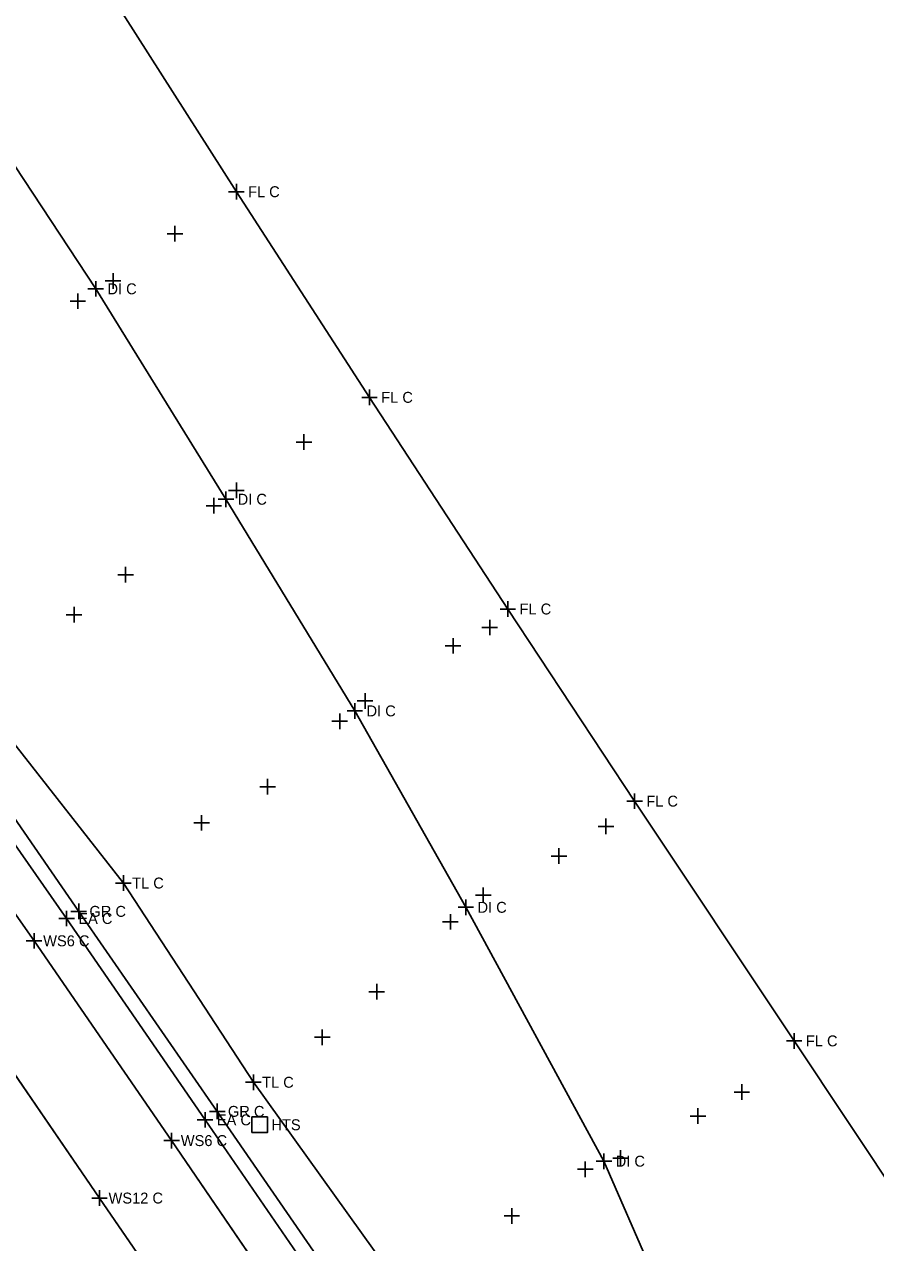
# Model space of a CAD drawing. Extents: x 1324236 to 1326110, y 459090 to 460782.
# Drawn here: x 1325473.8 to 1325582.8, y 460147.8 to 460303.9 of the extents above; entities that cross this region are included whole.
import ezdxf

# ---------------------------------------------------------------- set-up
doc = ezdxf.new("R2010")
doc.units = 0
for name, color, linetype in [('DR_X_Ditch', 7, 'Continuous'), ('DR_X_Drive_Pipe', 7, 'Continuous'), ('DR_X_Storm_Sewer', 7, 'Continuous'), ('DT_X_Contour_Major', 7, 'Continuous'), ('DV_X_Property_Line', 7, 'Continuous'), ('LT_X_Poles', 7, 'Continuous'), ('PM_X_CL_Double_Solid', 7, 'Continuous'), ('PM_X_Edge_Line', 7, 'Continuous'), ('PM_X_Parking_Lot_Stall', 7, 'Continuous'), ('PV_X_Shoulder', 7, 'Continuous'), ('RD_X_GR_Lt', 7, 'Continuous'), ('RW_X_CL', 7, 'Continuous'), ('RW_X_Esmt_SH', 7, 'Continuous')]:
    doc.layers.add(name, color=color, linetype=linetype)

msp = doc.modelspace()

# ---------------------------------------------------------------- linework, layer by layer
at = {"layer": 'DR_X_Ditch'}
msp.add_lwpolyline([(1325392.48, 460306.14), (1325394.43, 460302.92), (1325394.43, 460302.92), (1325397.79, 460297.88), (1325401.32, 460292.96), (1325401.32, 460292.96), (1325418.59, 460267.6), (1325438.59, 460238.95), (1325456.84, 460212.47), (1325475.03, 460186.5), (1325492.65, 460160.91), (1325510.99, 460134.02), (1325529.23, 460107.34), (1325547.28, 460081.09), (1325565.79, 460054.08), (1325584.28, 460027.39)], dxfattribs=at)
at = {"layer": 'DR_X_Drive_Pipe'}
for p, q in [((1325463.76, 460299.09), (1325482.93, 460270.01)), ((1325482.93, 460270.01), (1325499.6, 460243.06)), ((1325499.6, 460243.06), (1325516.1, 460215.95)), ((1325516.1, 460215.95), (1325530.31, 460190.79)), ((1325530.31, 460190.79), (1325548, 460158.27)), ((1325548, 460158.27), (1325558.06, 460135.19))]:
    msp.add_line(p, q, dxfattribs=at)
at = {"layer": 'DR_X_Storm_Sewer'}
for p, q in [((1325483.41, 460153.55), (1325465.49, 460179.7)), ((1325501.6, 460127.06), (1325483.41, 460153.55))]:
    msp.add_line(p, q, dxfattribs=at)
at = {"layer": 'DT_X_Contour_Major'}
msp.add_line((1325503.92, 460162.94), (1325503.92, 460162.94), dxfattribs=at)
msp.add_lwpolyline([(1325502.92, 460161.94), (1325502.92, 460163.94), (1325504.92, 460163.94), (1325504.92, 460161.94), (1325502.92, 460161.94)], dxfattribs=at)
at = {"layer": 'DV_X_Property_Line'}
for p, q in [((1325479.2, 460188.36), (1325479.2, 460190.36)), ((1325478.2, 460189.36), (1325480.2, 460189.36)), ((1325496.93, 460162.57), (1325496.93, 460164.57)), ((1325495.93, 460163.57), (1325497.93, 460163.57))]:
    msp.add_line(p, q, dxfattribs=at)
at = {"layer": 'LT_X_Poles'}
for points in [[(1325552.53, 460052.37), (1325537.68, 460074.22), (1325518.91, 460101.44), (1325501.6, 460127.06), (1325483.41, 460153.55), (1325465.49, 460179.7), (1325447.45, 460205.76), (1325428.78, 460232.55), (1325409.11, 460260.88), (1325391.07, 460286.18), (1325376.81, 460306.09), (1325363.64, 460323.93)], [(1325392.48, 460306.14), (1325394.43, 460302.92), (1325394.43, 460302.92), (1325397.79, 460297.88), (1325401.32, 460292.96), (1325401.32, 460292.96), (1325418.59, 460267.6), (1325438.59, 460238.95), (1325456.84, 460212.47), (1325475.03, 460186.5), (1325492.65, 460160.91), (1325510.99, 460134.02), (1325529.23, 460107.34), (1325547.28, 460081.09), (1325565.79, 460054.08), (1325584.28, 460027.39)]]:
    msp.add_lwpolyline(points, dxfattribs=at)
at = {"layer": 'PM_X_CL_Double_Solid'}
for p, q in [((1325486.43, 460305.19), (1325500.93, 460282.45)), ((1325500.93, 460282.45), (1325517.98, 460256.11)), ((1325517.98, 460256.11), (1325535.69, 460229)), ((1325535.69, 460229), (1325551.92, 460204.39)), ((1325551.92, 460204.39), (1325572.35, 460173.68)), ((1325572.35, 460173.68), (1325587.79, 460150.43))]:
    msp.add_line(p, q, dxfattribs=at)
at = {"layer": 'PM_X_Edge_Line'}
for p, q in [((1325456.84, 460212.47), (1325475.03, 460186.5)), ((1325475.03, 460186.5), (1325492.65, 460160.91)), ((1325492.65, 460160.91), (1325510.99, 460134.02))]:
    msp.add_line(p, q, dxfattribs=at)
at = {"layer": 'PM_X_Parking_Lot_Stall'}
for p, q in [((1325462.39, 460216.88), (1325480.76, 460190.27)), ((1325480.76, 460190.27), (1325498.49, 460164.65)), ((1325498.49, 460164.65), (1325517.01, 460137.81))]:
    msp.add_line(p, q, dxfattribs=at)
at = {"layer": 'PV_X_Shoulder'}
msp.add_lwpolyline([(1325398.37, 460305.69), (1325405.2, 460296.15), (1325405.2, 460296.15), (1325422.82, 460270.39), (1325442.8, 460241.71), (1325461.19, 460215.15), (1325479.2, 460189.36), (1325496.93, 460163.57), (1325515.23, 460136.92), (1325533.46, 460110.33), (1325551.75, 460083.69), (1325569.83, 460056.87), (1325588.2, 460030.22)], dxfattribs=at)
at = {"layer": 'RD_X_GR_Lt'}
for p, q in [((1325486.47, 460193.9), (1325466.66, 460219.16)), ((1325503.11, 460168.38), (1325486.47, 460193.9)), ((1325522.24, 460141.73), (1325503.11, 460168.38))]:
    msp.add_line(p, q, dxfattribs=at)
at = {"layer": 'RW_X_CL'}
for p, q in [((1325493.07, 460276.06), (1325493.07, 460278.06)), ((1325492.07, 460277.06), (1325494.07, 460277.06)), ((1325485.14, 460270.03), (1325485.14, 460272.03)), ((1325484.14, 460271.03), (1325486.14, 460271.03)), ((1325479.64, 460268.43), (1325481.64, 460268.43)), ((1325480.64, 460267.43), (1325480.64, 460269.43)), ((1325509.59, 460249.38), (1325509.59, 460251.38)), ((1325508.59, 460250.38), (1325510.59, 460250.38)), ((1325500.93, 460243.19), (1325500.93, 460245.19)), ((1325499.93, 460244.19), (1325501.93, 460244.19)), ((1325497.05, 460242.22), (1325499.05, 460242.22)), ((1325498.05, 460241.22), (1325498.05, 460243.22)), ((1325486.76, 460232.39), (1325486.76, 460234.39)), ((1325485.76, 460233.39), (1325487.76, 460233.39)), ((1325479.16, 460228.26), (1325481.16, 460228.26)), ((1325480.16, 460227.26), (1325480.16, 460229.26)), ((1325532.38, 460226.63), (1325534.38, 460226.63)), ((1325533.38, 460225.63), (1325533.38, 460227.63)), ((1325528.68, 460223.28), (1325528.68, 460225.28)), ((1325527.68, 460224.28), (1325529.68, 460224.28)), ((1325516.41, 460217.23), (1325518.41, 460217.23)), ((1325517.41, 460216.23), (1325517.41, 460218.23)), ((1325514.17, 460213.63), (1325514.17, 460215.63)), ((1325513.17, 460214.63), (1325515.17, 460214.63)), ((1325503.94, 460206.24), (1325505.94, 460206.24)), ((1325504.94, 460205.24), (1325504.94, 460207.24)), ((1325495.49, 460201.61), (1325497.49, 460201.61)), ((1325496.49, 460200.61), (1325496.49, 460202.61)), ((1325548.25, 460200.15), (1325548.25, 460202.15)), ((1325547.25, 460201.15), (1325549.25, 460201.15)), ((1325542.23, 460196.36), (1325542.23, 460198.36)), ((1325541.23, 460197.36), (1325543.23, 460197.36)), ((1325531.54, 460192.35), (1325533.54, 460192.35)), ((1325532.54, 460191.35), (1325532.54, 460193.35)), ((1325527.34, 460188.93), (1325529.34, 460188.93)), ((1325528.34, 460187.93), (1325528.34, 460189.93)), ((1325475.03, 460185.5), (1325475.03, 460187.5)), ((1325474.03, 460186.5), (1325476.03, 460186.5)), ((1325518.91, 460178.97), (1325518.91, 460180.97)), ((1325517.91, 460179.97), (1325519.91, 460179.97)), ((1325511.94, 460173.14), (1325511.94, 460175.14)), ((1325510.94, 460174.14), (1325512.94, 460174.14)), ((1325564.65, 460167.12), (1325566.65, 460167.12)), ((1325565.65, 460166.12), (1325565.65, 460168.12)), ((1325559.02, 460164.06), (1325561.02, 460164.06)), ((1325560.02, 460163.06), (1325560.02, 460165.06)), ((1325491.65, 460160.91), (1325493.65, 460160.91)), ((1325492.65, 460159.91), (1325492.65, 460161.91)), ((1325550.12, 460157.67), (1325550.12, 460159.67)), ((1325545.61, 460156.23), (1325545.61, 460158.23)), ((1325549.12, 460158.67), (1325551.12, 460158.67)), ((1325544.61, 460157.23), (1325546.61, 460157.23)), ((1325483.41, 460152.55), (1325483.41, 460154.55)), ((1325482.41, 460153.55), (1325484.41, 460153.55)), ((1325536.2, 460150.26), (1325536.2, 460152.26)), ((1325535.2, 460151.26), (1325537.2, 460151.26))]:
    msp.add_line(p, q, dxfattribs=at)
at = {"layer": 'RW_X_Esmt_SH'}
for p, q in [((1325499.93, 460282.45), (1325501.93, 460282.45)), ((1325500.93, 460281.45), (1325500.93, 460283.45)), ((1325481.93, 460270.01), (1325483.93, 460270.01)), ((1325482.93, 460269.01), (1325482.93, 460271.01)), ((1325516.98, 460256.11), (1325518.98, 460256.11)), ((1325517.98, 460255.11), (1325517.98, 460257.11)), ((1325499.6, 460242.06), (1325499.6, 460244.06)), ((1325498.6, 460243.06), (1325500.6, 460243.06)), ((1325535.69, 460228), (1325535.69, 460230)), ((1325534.69, 460229), (1325536.69, 460229)), ((1325516.1, 460214.95), (1325516.1, 460216.95)), ((1325515.1, 460215.95), (1325517.1, 460215.95)), ((1325550.92, 460204.39), (1325552.92, 460204.39)), ((1325551.92, 460203.39), (1325551.92, 460205.39)), ((1325485.47, 460193.9), (1325487.47, 460193.9)), ((1325486.47, 460192.9), (1325486.47, 460194.9)), ((1325480.76, 460189.27), (1325480.76, 460191.27)), ((1325529.31, 460190.79), (1325531.31, 460190.79)), ((1325530.31, 460189.79), (1325530.31, 460191.79)), ((1325479.76, 460190.27), (1325481.76, 460190.27)), ((1325571.35, 460173.68), (1325573.35, 460173.68)), ((1325572.35, 460172.68), (1325572.35, 460174.68)), ((1325503.11, 460167.38), (1325503.11, 460169.38)), ((1325502.11, 460168.38), (1325504.11, 460168.38)), ((1325498.49, 460163.65), (1325498.49, 460165.65)), ((1325497.49, 460164.65), (1325499.49, 460164.65)), ((1325548, 460157.27), (1325548, 460159.27)), ((1325547, 460158.27), (1325549, 460158.27))]:
    msp.add_line(p, q, dxfattribs=at)

# ---------------------------------------------------------------- texts
at = {"layer": 'DT_X_Contour_Major'}
msp.add_text('HTS', height=1.4, dxfattribs=at).set_placement((1325505.42, 460162.24))
at = {"layer": 'DV_X_Property_Line'}
for p in [(1325480.7, 460188.66), (1325498.43, 460162.87)]:
    msp.add_text('EA C', height=1.4, dxfattribs=at).set_placement(p)
at = {"layer": 'RW_X_CL'}
for s, p in [('WS6 C', (1325476.2, 460185.8)), ('WS6 C', (1325493.82, 460160.21)), ('WS12 C', (1325484.57, 460152.85))]:
    msp.add_text(s, height=1.4, dxfattribs=at).set_placement(p)
at = {"layer": 'RW_X_Esmt_SH'}
for s, p in [('FL C', (1325502.43, 460281.75)), ('DI C', (1325484.43, 460269.31)), ('FL C', (1325519.48, 460255.41)), ('DI C', (1325501.1, 460242.36)), ('FL C', (1325537.19, 460228.3)), ('DI C', (1325517.6, 460215.25)), ('FL C', (1325553.42, 460203.69)), ('TL C', (1325487.59, 460193.2)), ('GR C', (1325482.12, 460189.57)), ('DI C', (1325531.81, 460190.09)), ('FL C', (1325573.85, 460172.98)), ('TL C', (1325504.23, 460167.68)), ('GR C', (1325499.85, 460163.95)), ('DI C', (1325549.5, 460157.57))]:
    msp.add_text(s, height=1.4, dxfattribs=at).set_placement(p)

doc.saveas('drawing.dxf')
